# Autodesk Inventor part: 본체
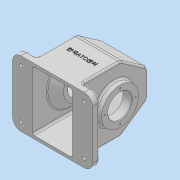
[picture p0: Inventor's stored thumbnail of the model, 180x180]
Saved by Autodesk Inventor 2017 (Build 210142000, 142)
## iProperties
Part Number: 본체
Material: 일반
Document SubType Name: Modeling
Designer: MRC
Density: 1 g/cm^3
Appearance: 기본값
Author: MRC
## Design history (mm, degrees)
sketch "스케치1"
  geometry: L1 (-65, -55)-(12, -55); L2 (12, -55)-(57, -23.491); L3 (57, -23.491)-(57, 23.491); L4 (57, 23.491)-(12, 55); L5 (12, 55)-(-65, 55); L6 (-65, 55)-(-65, -55); 3 further points
  constraints: 12 end point, 2 horizontal alignment, 2 midpoint, 2 perpendicular, 1 horizontal, 1 parallel
  dimensions: "d0" = 65 distance from line of L6 point (0, 0); "d1" = 77 distance of L1.start L1.end; "d2" = 35 deg angle of L1 L2; "d3" = 35 deg angle of L5 L4; "d4" = 110 distance of L5.end L1.start; "d5" = 122 distance between parallel lines of L6 L3
extrude "돌출1" new body sketch "스케치1" stored distance "d6" = 77; taper "d7" = 0 deg
feature "쉘1" dims "d8" = 5
sketch "스케치2"
  geometry: L1 (0, 0)-(0, 110) reference; L2 (0, 110)-(-28.5, 110); L3 (-28.5, 110)-(-28.5, 0); L4 (-28.5, 0)-(0, 0); 1 further point
  constraints: 6 end point, 2 horizontal, 1 perpendicular
  dimensions: "d9" = 67 distance from line of point (38.5, 55) L3
extrude "돌출2" join sketch "스케치2" distance "d10" = 12; taper "d11" = 0 deg
sketch "스케치3"
  geometry: C1 r 37.5 at (0, 0); 1 further point
  constraints: 1 centre point, 1 coincident
  dimensions: "d12" = 75 diameter of C1
extrude "돌출3" join sketch "스케치3" distance "d13" = 5; taper "d14" = 0 deg
sketch "스케치5"
  geometry: C1 r 31 at (0, 0); 1 further point
  constraints: 1 centre point, 1 coincident
  dimensions: "d24" = 62 diameter of C1
extrude "돌출4" join sketch "스케치5" distance "d25" = 10; taper "d26" = 0 deg
node "작업 평면1"
sketch "스케치6"
  geometry: C1 r 27 at (0, 0); 1 further point
  constraints: 1 centre point, 1 coincident
  dimensions: "d28" = 54 diameter of C1
extrude "돌출5" join sketch "스케치6" stored distance "d29" = 10; taper "d30" = 45 deg
hole "구멍2" diameter "d33" = 40; stored, may be unused: countersink angle "d37" = 90 deg, drill point angle "d39" = 118 deg; dims "d31" = 10, "d32" = 10, "d34" = 6, "d35" = 4, "d36" = 2, "d38" = 24
hole "구멍3" diameter "d42" = 40; stored, may be unused: countersink angle "d46" = 90 deg, drill point angle "d48" = 118 deg; dims "d40" = 10, "d41" = 10, "d43" = 6, "d44" = 4, "d45" = 2, "d47" = 15
sketch "스케치7"
  geometry: C1 r 6 at (38.5, 23.491); 1 further point
  constraints: 1 centre point, 1 coincident
  dimensions: "d49" = 12 diameter of C1
extrude "돌출6" join sketch "스케치7" distance "d50" = 4; taper "d51" = 0 deg
sketch "스케치8"
  geometry: A1 r 29 centre (0, 0) between (0, 29) and (29, 0); 3 further points
  constraints: 4 point on circle, 2 horizontal alignment, 2 vertical alignment, 1 centre point, 1 coincident
  dimensions: "d52" = 58 diameter of A1
hole "구멍4" sketch "스케치8" at (0, 29), (29, 0), (0, -29), (-29, 0) diameter "d53" = 2.459; stored, may be unused: countersink angle "d57" = 90 deg, drill point angle "d59" = 118 deg; dims "d54" = 6, "d55" = 4, "d56" = 2, "d58" = 8
sketch "스케치9"
  geometry: A1 r 26 centre (0, 0) between (0, 26) and (26, 0); 3 further points
  constraints: 4 point on circle, 2 horizontal alignment, 2 vertical alignment, 1 centre point, 1 coincident
  dimensions: "d60" = 52 diameter of A1
hole "구멍5" sketch "스케치9" at (0, 26), (26, 0), (0, -26), (-26, 0) diameter "d61" = 2.459; stored, may be unused: countersink angle "d65" = 90 deg, drill point angle "d67" = 118 deg; dims "d62" = 6, "d63" = 4, "d64" = 2, "d66" = 8.8
hole "구멍6" diameter "d70" = 5.188; stored, may be unused: countersink angle "d74" = 90 deg, drill point angle "d76" = 118 deg; dims "d68" = 10, "d69" = 10, "d71" = 12, "d72" = 4, "d73" = 2, "d75" = 31
fillet "모깎기1" dims "d77" = 10
fillet "모깎기8" dims "d92" = 14
sketch "스케치11"
  geometry: L1 (-28.5, -96)-(-28.5, -14) reference; L2 (5, -5)-(5, -105) reference; L3 (5, -105)-(72, -105) reference; L4 (72, -105)-(72, -5) reference; L5 (72, -5)-(5, -5) reference; L6 (-28.5, -96)-(-28.5, -14) reference; L7 (91.5, 0)-(-14.5, 0) reference; L8 (105.5, -96)-(105.5, -14) reference; L9 (-14.5, -110)-(91.5, -110) reference; A1 r 14 centre (-14.5, -14) between (-14.5, 0) and (-28.5, -14) reference; A2 r 14 centre (-14.5, -96) between (-28.5, -96) and (-14.5, -110) reference; A3 r 14 centre (-14.5, -96) between (-28.5, -96) and (-14.5, -110) reference; A4 r 14 centre (-14.5, -14) between (-14.5, 0) and (-28.5, -14) reference; A5 r 14 centre (91.5, -14) between (105.5, -14) and (91.5, 0) reference; A6 r 14 centre (91.5, -96) between (91.5, -110) and (105.5, -96) reference; 5 further points
  constraints: 4 coincident
hole "구멍7" sketch "스케치11" at (-14.5, -14), (-14.5, -96), (91.5, -96), (91.5, -14) diameter "d93" = 5.5; stored, may be unused: countersink angle "d97" = 90 deg, drill point angle "d99" = 118 deg; dims "d94" = 12, "d95" = 15, "d96" = 2, "d98" = 31
fillet "모깎기4" dims "d80" = 3
chamfer "모따기1" distance "d81" = 1; stored, may be unused: second distance "d82" = 2, angle "d83" = 45 deg
fillet "모깎기5" dims "d84" = 5
fillet "모깎기6" dims "d85" = 3
fillet "모깎기7" dims "d86" = 3
fillet "모깎기9" dims "d101" = 3
node "작업 평면5"
sketch "스케치13" dims "d0" = 65, "d1" = 77, "d2" = 35 deg, "d3" = 35 deg, "d4" = 110, "d5" = 122
  geometry: L1 (14.5, 73.847)-(14.5, 15) reference; L2 (0, 0)-(106, 0) reference; 2 further points
  constraints: 1 other
  dimensions: "d103" = 38.5 distance from line of point (53, 50) L1; "d104" = 50 distance from line of point (53, 50) L2
feature "엠보싱2" sketch "스케치13" dims "d105" = 0.5, "d106" = 0
node "솔리드1"
mirror "미러1"
node "투영된 루프1"
other parameters: "d27" = -24
